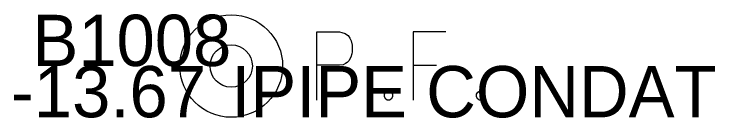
# Model space of a CAD drawing. Extents: x 2177554 to 2180444, y 721535 to 723442.
# Drawn here: x 2180235.656 to 2180236.473, y 723441.925 to 723442.047 of the extents above; entities that cross this region are included whole.
import ezdxf

# ---------------------------------------------------------------- set-up
doc = ezdxf.new("R2010")
doc.units = 0
for name, color, linetype in [('SV_X_Mon_Cells_Found', 7, 'Continuous'), ('SV_X_Text_Comment', 7, 'Continuous'), ('SV_X_Text_Elevation', 7, 'Continuous'), ('SV_X_Text_Name', 7, 'Continuous')]:
    doc.layers.add(name, color=color, linetype=linetype)

msp = doc.modelspace()

# ---------------------------------------------------------------- linework, layer by layer
at = {"layer": 'SV_X_Mon_Cells_Found'}
for points in [[(2180236.00886, 723441.946), (2180236.00886, 723442.026), (2180236.03531, 723442.026), (2180236.03807, 723442.02537), (2180236.04193, 723442.02411), (2180236.04359, 723442.02285), (2180236.04523, 723442.02159), (2180236.04744, 723442.01844), (2180236.0491, 723442.01529), (2180236.0502, 723442.01025), (2180236.0502, 723442.00269), (2180236.04964, 723442.00017), (2180236.04854, 723441.99639), (2180236.04634, 723441.99199), (2180236.04413, 723441.99009), (2180236.04248, 723441.98883), (2180236.03972, 723441.98757), (2180236.03531, 723441.98695), (2180236.00886, 723441.98695)], [(2180236.15933, 723442.026), (2180236.12129, 723442.026), (2180236.12129, 723441.946)], [(2180236.12129, 723441.98695), (2180236.1483, 723441.98695)], [(2180236.09098, 723441.95671), (2180236.09374, 723441.95671), (2180236.09539, 723441.95545), (2180236.09704, 723441.95293), (2180236.09704, 723441.94978), (2180236.09539, 723441.94726), (2180236.09374, 723441.946), (2180236.09098, 723441.946), (2180236.08933, 723441.94726), (2180236.08768, 723441.94978), (2180236.08768, 723441.95293), (2180236.08933, 723441.95545), (2180236.09098, 723441.95671)], [(2180236.19845, 723441.95671), (2180236.2012, 723441.95671), (2180236.20286, 723441.95545), (2180236.20451, 723441.95293), (2180236.20451, 723441.94978), (2180236.20286, 723441.94726), (2180236.2012, 723441.946), (2180236.19845, 723441.946), (2180236.1968, 723441.94726), (2180236.19515, 723441.94978), (2180236.19515, 723441.95293), (2180236.1968, 723441.95545), (2180236.19845, 723441.95671)]]:
    msp.add_lwpolyline(points, dxfattribs=at)
for centre, radius in [((2180235.909, 723441.986), 0.06), ((2180235.90899, 723441.98599), 0.02474)]:
    msp.add_circle(centre, radius, dxfattribs=at)

# ---------------------------------------------------------------- texts
at = {"layer": 'SV_X_Text_Comment'}
msp.add_text('IPIPE CONDAT', height=0.06, dxfattribs=at).set_placement((2180235.909, 723441.926))
at = {"layer": 'SV_X_Text_Elevation'}
msp.add_text('-13.67', height=0.06, dxfattribs=at).set_placement((2180235.65204, 723441.926))
at = {"layer": 'SV_X_Text_Name'}
msp.add_text('B1008', height=0.06, dxfattribs=at).set_placement((2180235.67708, 723441.986))

doc.saveas('drawing.dxf')
